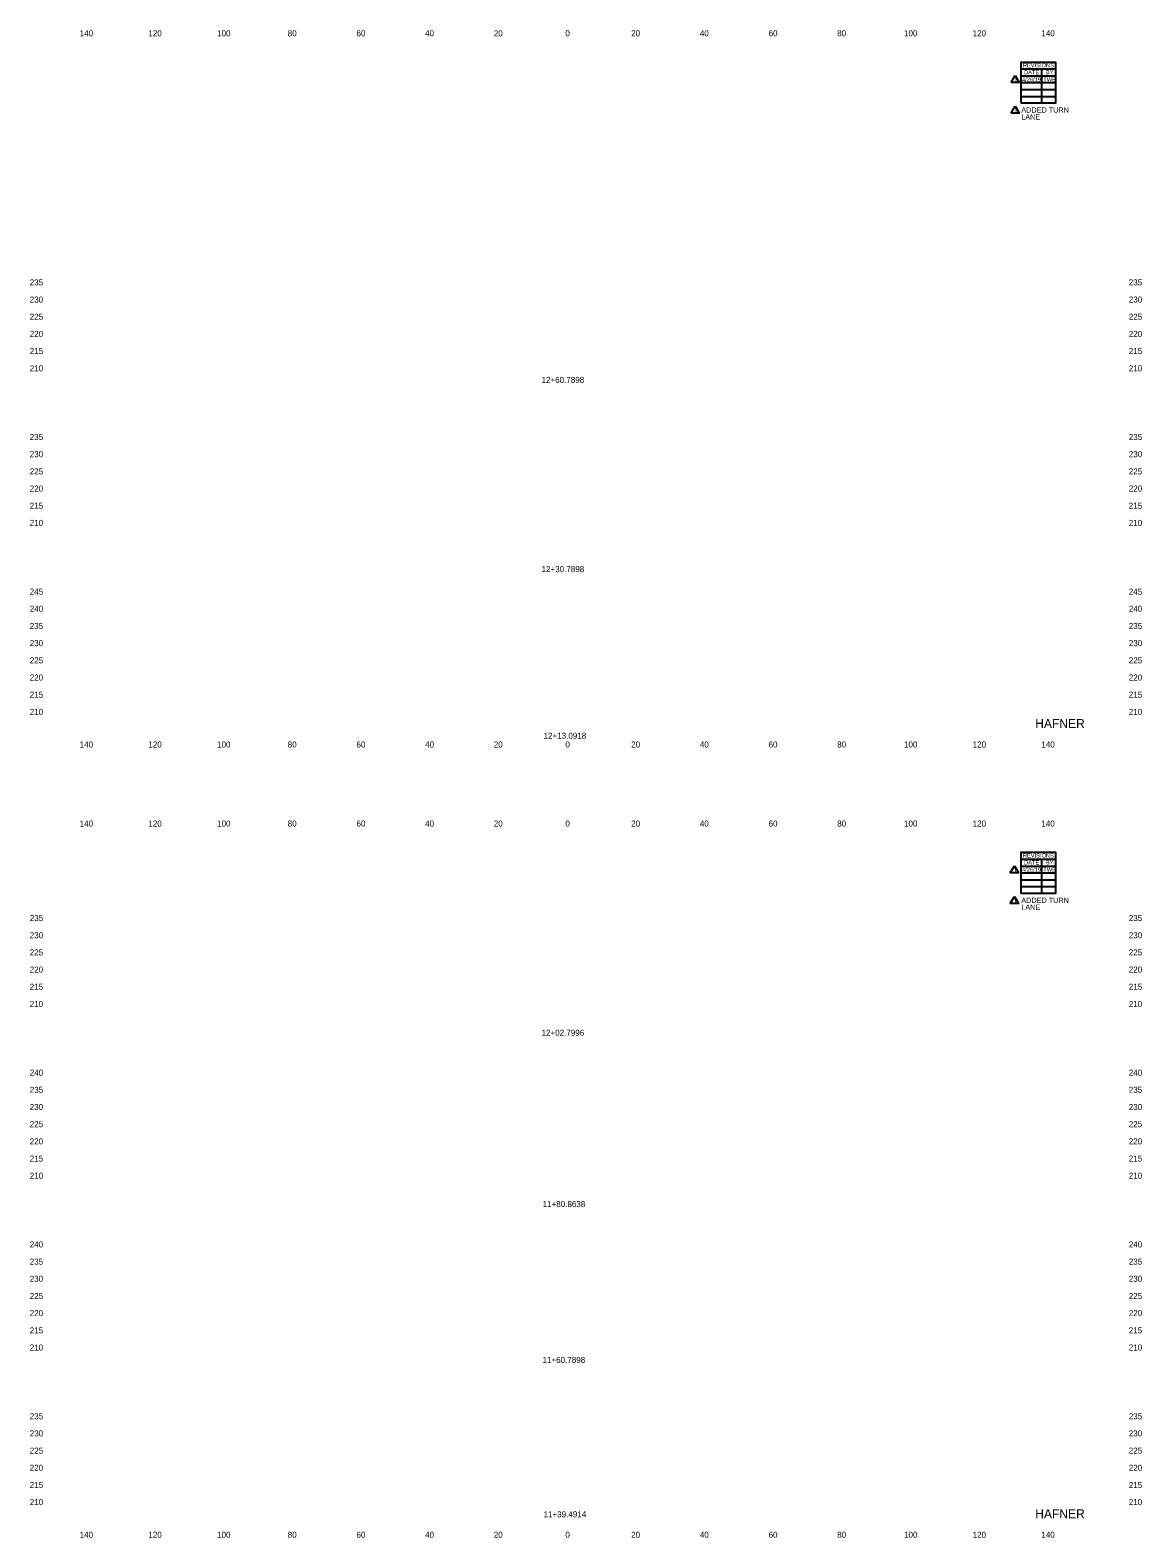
# Model space of a CAD drawing. Extents: x 2937 to 3260, y 834 to 1273.
import ezdxf

# ---------------------------------------------------------------- set-up
doc = ezdxf.new("R2010")
doc.units = 0
for name, color, linetype in [('ROW_REVISION_DATA', 7, 'Continuous'), ('XS_SHEET_LABELS_ELEVATION', 7, 'Continuous'), ('XS_SHEET_LABELS_OFFSET', 7, 'Continuous'), ('XS_SHEET_LABELS_STATION', 7, 'Continuous')]:
    doc.layers.add(name, color=color, linetype=linetype)

msp = doc.modelspace()

# ---------------------------------------------------------------- linework, layer by layer
at = {"layer": 'ROW_REVISION_DATA'}
for p, q in [((3222.33, 1257.32), (3223.53, 1259.4)), ((3225.31, 1261.29), (3235.31, 1261.29)), ((3231.31, 1251.29), (3231.31, 1261.29)), ((3235.31, 1263.29), (3235.31, 1251.29)), ((3225.31, 1259.29), (3235.31, 1259.29)), ((3225.31, 1257.29), (3235.31, 1257.29)), ((3225.31, 1255.29), (3235.31, 1255.29)), ((3231.31, 1255.29), (3231.31, 1255.29)), ((3225.31, 1253.29), (3235.31, 1253.29)), ((3222.33, 1248.4), (3223.53, 1250.48)), ((3225.31, 1031.29), (3235.31, 1031.29)), ((3231.31, 1021.29), (3231.31, 1031.29)), ((3235.31, 1033.29), (3235.31, 1021.29)), ((3222.12, 1027.27), (3223.32, 1029.35)), ((3225.31, 1029.29), (3235.31, 1029.29)), ((3225.31, 1027.29), (3235.31, 1027.29)), ((3225.31, 1025.29), (3235.31, 1025.29)), ((3225.31, 1023.29), (3235.31, 1023.29)), ((3231.31, 1025.29), (3231.31, 1025.29)), ((3222.12, 1018.35), (3223.32, 1020.43))]:
    msp.add_line(p, q, dxfattribs=at)
for points in [[(3223.53, 1259.4), (3224.73, 1257.32), (3222.33, 1257.32)], [(3223.53, 1250.48), (3224.73, 1248.4), (3222.33, 1248.4)], [(3223.32, 1029.35), (3224.52, 1027.27), (3222.12, 1027.27)], [(3223.32, 1020.43), (3224.52, 1018.35), (3222.12, 1018.35)]]:
    msp.add_lwpolyline(points, dxfattribs=at)
for points in [[(3225.31, 1251.29), (3225.31, 1263.29), (3235.31, 1263.29), (3235.31, 1251.29)], [(3225.31, 1021.29), (3225.31, 1033.29), (3235.31, 1033.29), (3235.31, 1021.29)]]:
    msp.add_lwpolyline(points, close=True, dxfattribs=at)

# ---------------------------------------------------------------- texts
for s, height, p in [('REVISIONS', 1.2, (3225.79, 1261.76)), ('DATE', 1.2, (3226.13, 1259.74)), ('BY', 1.2, (3232.46, 1259.75)), ('1', 1.32, (3223.26, 1257.47)), ('4/26/19 ', 1.2, (3225.51, 1257.63)), ('TWB', 1.2, (3231.73, 1257.63)), ('1', 1.32, (3223.26, 1248.55)), ('REVISIONS', 1.2, (3225.79, 1031.76)), ('1', 1.32, (3223.05, 1027.42)), ('4/26/19 ', 1.2, (3225.51, 1027.63)), ('DATE', 1.2, (3226.13, 1029.74)), ('TWB', 1.2, (3231.73, 1027.63)), ('BY', 1.2, (3232.46, 1029.75)), ('1', 1.32, (3223.05, 1018.5))]:
    msp.add_text(s, height=height, dxfattribs=at).set_placement(p)
for s, p in [('ADDED TURN', (3225.31, 1248.56)), ('LANE', (3225.31, 1246.55)), ('ADDED TURN', (3225.31, 1018.56)), ('LANE', (3225.31, 1016.55))]:
    msp.add_text(s, height=1.534, rotation=359.9626, dxfattribs=at).set_placement(p)
at = {"layer": 'XS_SHEET_LABELS_ELEVATION'}
for s, p in [('  235  ', (2935.31, 1198.29)), ('  235  ', (3255.31, 1198.29)), ('  230  ', (2935.31, 1193.29)), ('  230  ', (3255.31, 1193.29)), ('  225  ', (2935.31, 1188.29)), ('  225  ', (3255.31, 1188.29)), ('  220  ', (2935.31, 1183.29)), ('  220  ', (3255.31, 1183.29)), ('  215  ', (2935.31, 1178.29)), ('  215  ', (3255.31, 1178.29)), ('  210  ', (2935.31, 1173.29)), ('  210  ', (3255.31, 1173.29)), ('  235  ', (2935.31, 1153.29)), ('  235  ', (3255.31, 1153.29)), ('  230  ', (2935.31, 1148.29)), ('  230  ', (3255.31, 1148.29)), ('  225  ', (2935.31, 1143.29)), ('  225  ', (3255.31, 1143.29)), ('  220  ', (2935.31, 1138.29)), ('  220  ', (3255.31, 1138.29)), ('  215  ', (2935.31, 1133.29)), ('  215  ', (3255.31, 1133.29)), ('  210  ', (2935.31, 1128.29)), ('  210  ', (3255.31, 1128.29)), ('  245  ', (2935.31, 1108.29)), ('  245  ', (3255.31, 1108.29)), ('  240  ', (2935.31, 1103.29)), ('  240  ', (3255.31, 1103.29)), ('  235  ', (2935.31, 1098.29)), ('  235  ', (3255.31, 1098.29)), ('  230  ', (2935.31, 1093.29)), ('  230  ', (3255.31, 1093.29)), ('  225  ', (2935.31, 1088.29)), ('  225  ', (3255.31, 1088.29)), ('  220  ', (2935.31, 1083.29)), ('  220  ', (3255.31, 1083.29)), ('  215  ', (2935.31, 1078.29)), ('  215  ', (3255.31, 1078.29)), ('  210  ', (2935.31, 1073.29)), ('  210  ', (3255.31, 1073.29)), ('  235  ', (2935.31, 1013.29)), ('  235  ', (3255.31, 1013.29)), ('  230  ', (2935.31, 1008.29)), ('  230  ', (3255.31, 1008.29)), ('  225  ', (2935.31, 1003.29)), ('  225  ', (3255.31, 1003.29)), ('  220  ', (2935.31, 998.29)), ('  220  ', (3255.31, 998.29)), ('  215  ', (2935.31, 993.29)), ('  215  ', (3255.31, 993.29)), ('  210  ', (2935.31, 988.29)), ('  210  ', (3255.31, 988.29)), ('  240  ', (2935.31, 968.29)), ('  240  ', (3255.31, 968.29)), ('  235  ', (2935.31, 963.29)), ('  235  ', (3255.31, 963.29)), ('  230  ', (2935.31, 958.29)), ('  230  ', (3255.31, 958.29)), ('  225  ', (2935.31, 953.29)), ('  225  ', (3255.31, 953.29)), ('  220  ', (2935.31, 948.29)), ('  220  ', (3255.31, 948.29)), ('  215  ', (2935.31, 943.29)), ('  215  ', (3255.31, 943.29)), ('  210  ', (2935.31, 938.29)), ('  210  ', (3255.31, 938.29)), ('  240  ', (2935.31, 918.29)), ('  240  ', (3255.31, 918.29)), ('  235  ', (2935.31, 913.29)), ('  235  ', (3255.31, 913.29)), ('  230  ', (2935.31, 908.29)), ('  230  ', (3255.31, 908.29)), ('  225  ', (2935.31, 903.29)), ('  225  ', (3255.31, 903.29)), ('  220  ', (2935.31, 898.29)), ('  220  ', (3255.31, 898.29)), ('  215  ', (2935.31, 893.29)), ('  215  ', (3255.31, 893.29)), ('  210  ', (2935.31, 888.29)), ('  210  ', (3255.31, 888.29)), ('  235  ', (2935.31, 868.29)), ('  235  ', (3255.31, 868.29)), ('  230  ', (2935.31, 863.29)), ('  230  ', (3255.31, 863.29)), ('  225  ', (2935.31, 858.29)), ('  225  ', (3255.31, 858.29)), ('  220  ', (2935.31, 853.29)), ('  220  ', (3255.31, 853.29)), ('  215  ', (2935.31, 848.29)), ('  215  ', (3255.31, 848.29)), ('  210  ', (2935.31, 843.29)), ('  210  ', (3255.31, 843.29))]:
    msp.add_text(s, height=1.75, dxfattribs=at).set_placement(p)
at = {"layer": 'XS_SHEET_LABELS_OFFSET'}
for s, height, p in [('  140  ', 1.75, (2949.86, 1270.79)), ('  120  ', 1.75, (2969.86, 1270.79)), ('  100  ', 1.75, (2989.86, 1270.79)), ('  80  ', 1.75, (3010.42, 1270.79)), ('  60  ', 1.75, (3030.44, 1270.79)), ('  40  ', 1.75, (3050.42, 1270.79)), ('  20  ', 1.75, (3070.42, 1270.79)), ('  0  ', 1.75, (3091.28, 1270.79)), ('  0  ', 1.75, (3091.28, 1270.79)), ('  20  ', 1.75, (3110.42, 1270.79)), ('  40  ', 1.75, (3130.42, 1270.79)), ('  60  ', 1.75, (3150.44, 1270.79)), ('  80  ', 1.75, (3170.42, 1270.79)), ('  100  ', 1.75, (3189.86, 1270.79)), ('  120  ', 1.75, (3209.86, 1270.79)), ('  140  ', 1.75, (3229.86, 1270.79)), ('HAFNER', 2.625, (3229.37, 1069.46)), ('  140  ', 1.75, (2949.86, 1063.79)), ('  120  ', 1.75, (2969.86, 1063.79)), ('  100  ', 1.75, (2989.86, 1063.79)), ('  80  ', 1.75, (3010.42, 1063.79)), ('  60  ', 1.75, (3030.44, 1063.79)), ('  40  ', 1.75, (3050.42, 1063.79)), ('  20  ', 1.75, (3070.42, 1063.79)), ('  0  ', 1.75, (3091.28, 1063.79)), ('  0  ', 1.75, (3091.28, 1063.79)), ('  20  ', 1.75, (3110.42, 1063.79)), ('  40  ', 1.75, (3130.42, 1063.79)), ('  60  ', 1.75, (3150.44, 1063.79)), ('  80  ', 1.75, (3170.42, 1063.79)), ('  100  ', 1.75, (3189.86, 1063.79)), ('  120  ', 1.75, (3209.86, 1063.79)), ('  140  ', 1.75, (3229.86, 1063.79)), ('  140  ', 1.75, (2949.86, 1040.79)), ('  120  ', 1.75, (2969.86, 1040.79)), ('  100  ', 1.75, (2989.86, 1040.79)), ('  80  ', 1.75, (3010.42, 1040.79)), ('  60  ', 1.75, (3030.44, 1040.79)), ('  40  ', 1.75, (3050.42, 1040.79)), ('  20  ', 1.75, (3070.42, 1040.79)), ('  0  ', 1.75, (3091.28, 1040.79)), ('  0  ', 1.75, (3091.28, 1040.79)), ('  20  ', 1.75, (3110.42, 1040.79)), ('  40  ', 1.75, (3130.42, 1040.79)), ('  60  ', 1.75, (3150.44, 1040.79)), ('  80  ', 1.75, (3170.42, 1040.79)), ('  100  ', 1.75, (3189.86, 1040.79)), ('  120  ', 1.75, (3209.86, 1040.79)), ('  140  ', 1.75, (3229.86, 1040.79)), ('HAFNER', 2.625, (3229.37, 839.46)), ('  140  ', 1.75, (2949.86, 833.79)), ('  120  ', 1.75, (2969.86, 833.79)), ('  100  ', 1.75, (2989.86, 833.79)), ('  80  ', 1.75, (3010.42, 833.79)), ('  60  ', 1.75, (3030.44, 833.79)), ('  40  ', 1.75, (3050.42, 833.79)), ('  20  ', 1.75, (3070.42, 833.79)), ('  0  ', 1.75, (3091.28, 833.79)), ('  0  ', 1.75, (3091.28, 833.79)), ('  20  ', 1.75, (3110.42, 833.79)), ('  40  ', 1.75, (3130.42, 833.79)), ('  60  ', 1.75, (3150.44, 833.79)), ('  80  ', 1.75, (3170.42, 833.79)), ('  100  ', 1.75, (3189.86, 833.79)), ('  120  ', 1.75, (3209.86, 833.79)), ('  140  ', 1.75, (3229.86, 833.79))]:
    msp.add_text(s, height=height, dxfattribs=at).set_placement(p)
at = {"layer": 'XS_SHEET_LABELS_STATION'}
for s, p in [('  12+60.7898  ', (3084.32, 1169.91)), ('  12+30.7898  ', (3084.33, 1114.83)), ('  12+13.0918  ', (3084.91, 1066.33)), ('  12+02.7996  ', (3084.33, 979.89)), ('  11+80.8638  ', (3084.64, 930.03)), ('  11+60.7898  ', (3084.61, 884.68)), ('  11+39.4914  ', (3084.91, 839.74))]:
    msp.add_text(s, height=1.75, dxfattribs=at).set_placement(p)

doc.saveas('drawing.dxf')
